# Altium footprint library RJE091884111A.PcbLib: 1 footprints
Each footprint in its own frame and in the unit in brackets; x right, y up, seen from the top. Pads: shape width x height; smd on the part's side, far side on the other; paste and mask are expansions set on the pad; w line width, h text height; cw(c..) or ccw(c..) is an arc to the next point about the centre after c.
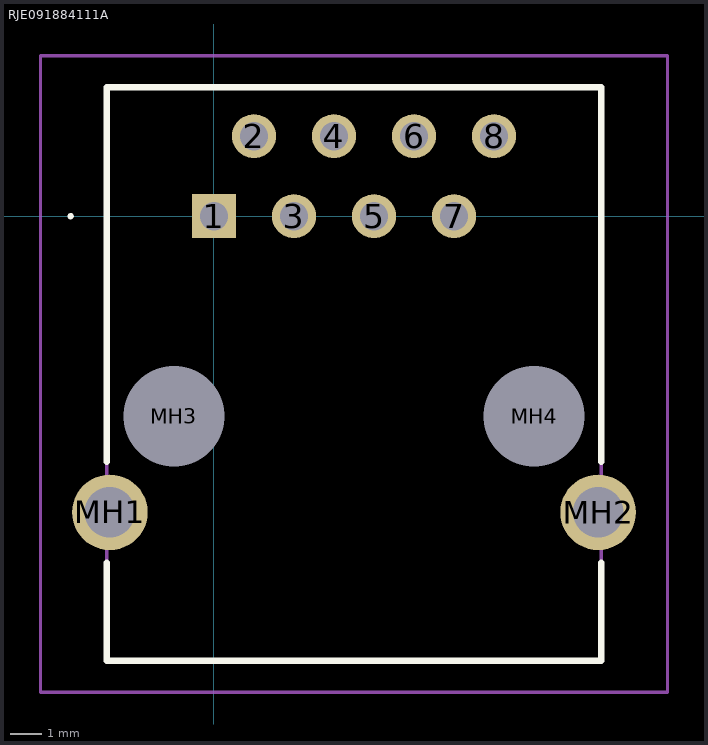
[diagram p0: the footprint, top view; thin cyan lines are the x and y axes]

## RJE091884111A [mm]
pads (12):
  rect 1.4x1.4 hole 0.9: 1(0,0)
  round 1.4 hole 0.9: 2(1.27,2.54) 3(2.54,0) 4(3.81,2.54) 5(5.08,0) 6(6.35,2.54) 7(7.62,0) 8(8.89,2.54)
  round 2.4 hole 1.6: MH1(-3.305,-9.4) MH2(12.195,-9.4)
  round 1.6 hole 3.2 unplated: MH3(-1.27,-6.35) MH4(10.16,-6.35)
Top Overlay:
  lines w0.1: -4.6,0 cw(c-4.55,0) -4.5,0 ; -4.6,0 -4.6,0 ; -4.6,0 ccw(c-4.55,0) -4.5,0 ; -4.5,0 -4.5,0
  lines w0.2: -3.405,-11 -3.405,-14.11 12.295,-14.11 12.295,-11 ; -3.4,-7.8 -3.405,4.09 12.295,4.09 12.295,-7.8
Mechanical 15:
  lines w0.1: -3.405,-14.11 12.295,-14.11 12.295,4.09 -3.405,4.09 -3.405,-14.11
Mechanical 20:
  lines w0.1: -5.505,-15.11 14.395,-15.11 14.395,5.09 -5.505,5.09 -5.505,-15.11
